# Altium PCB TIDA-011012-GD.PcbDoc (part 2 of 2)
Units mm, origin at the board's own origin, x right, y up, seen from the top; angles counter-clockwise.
Board outline 56 x 53 mm, 4 copper layers (Top Layer, Layer 1, Layer 2, Bottom Layer), stack 1.787 mm thick; 152 components, 63 nets, 416 pads, 728 vias.
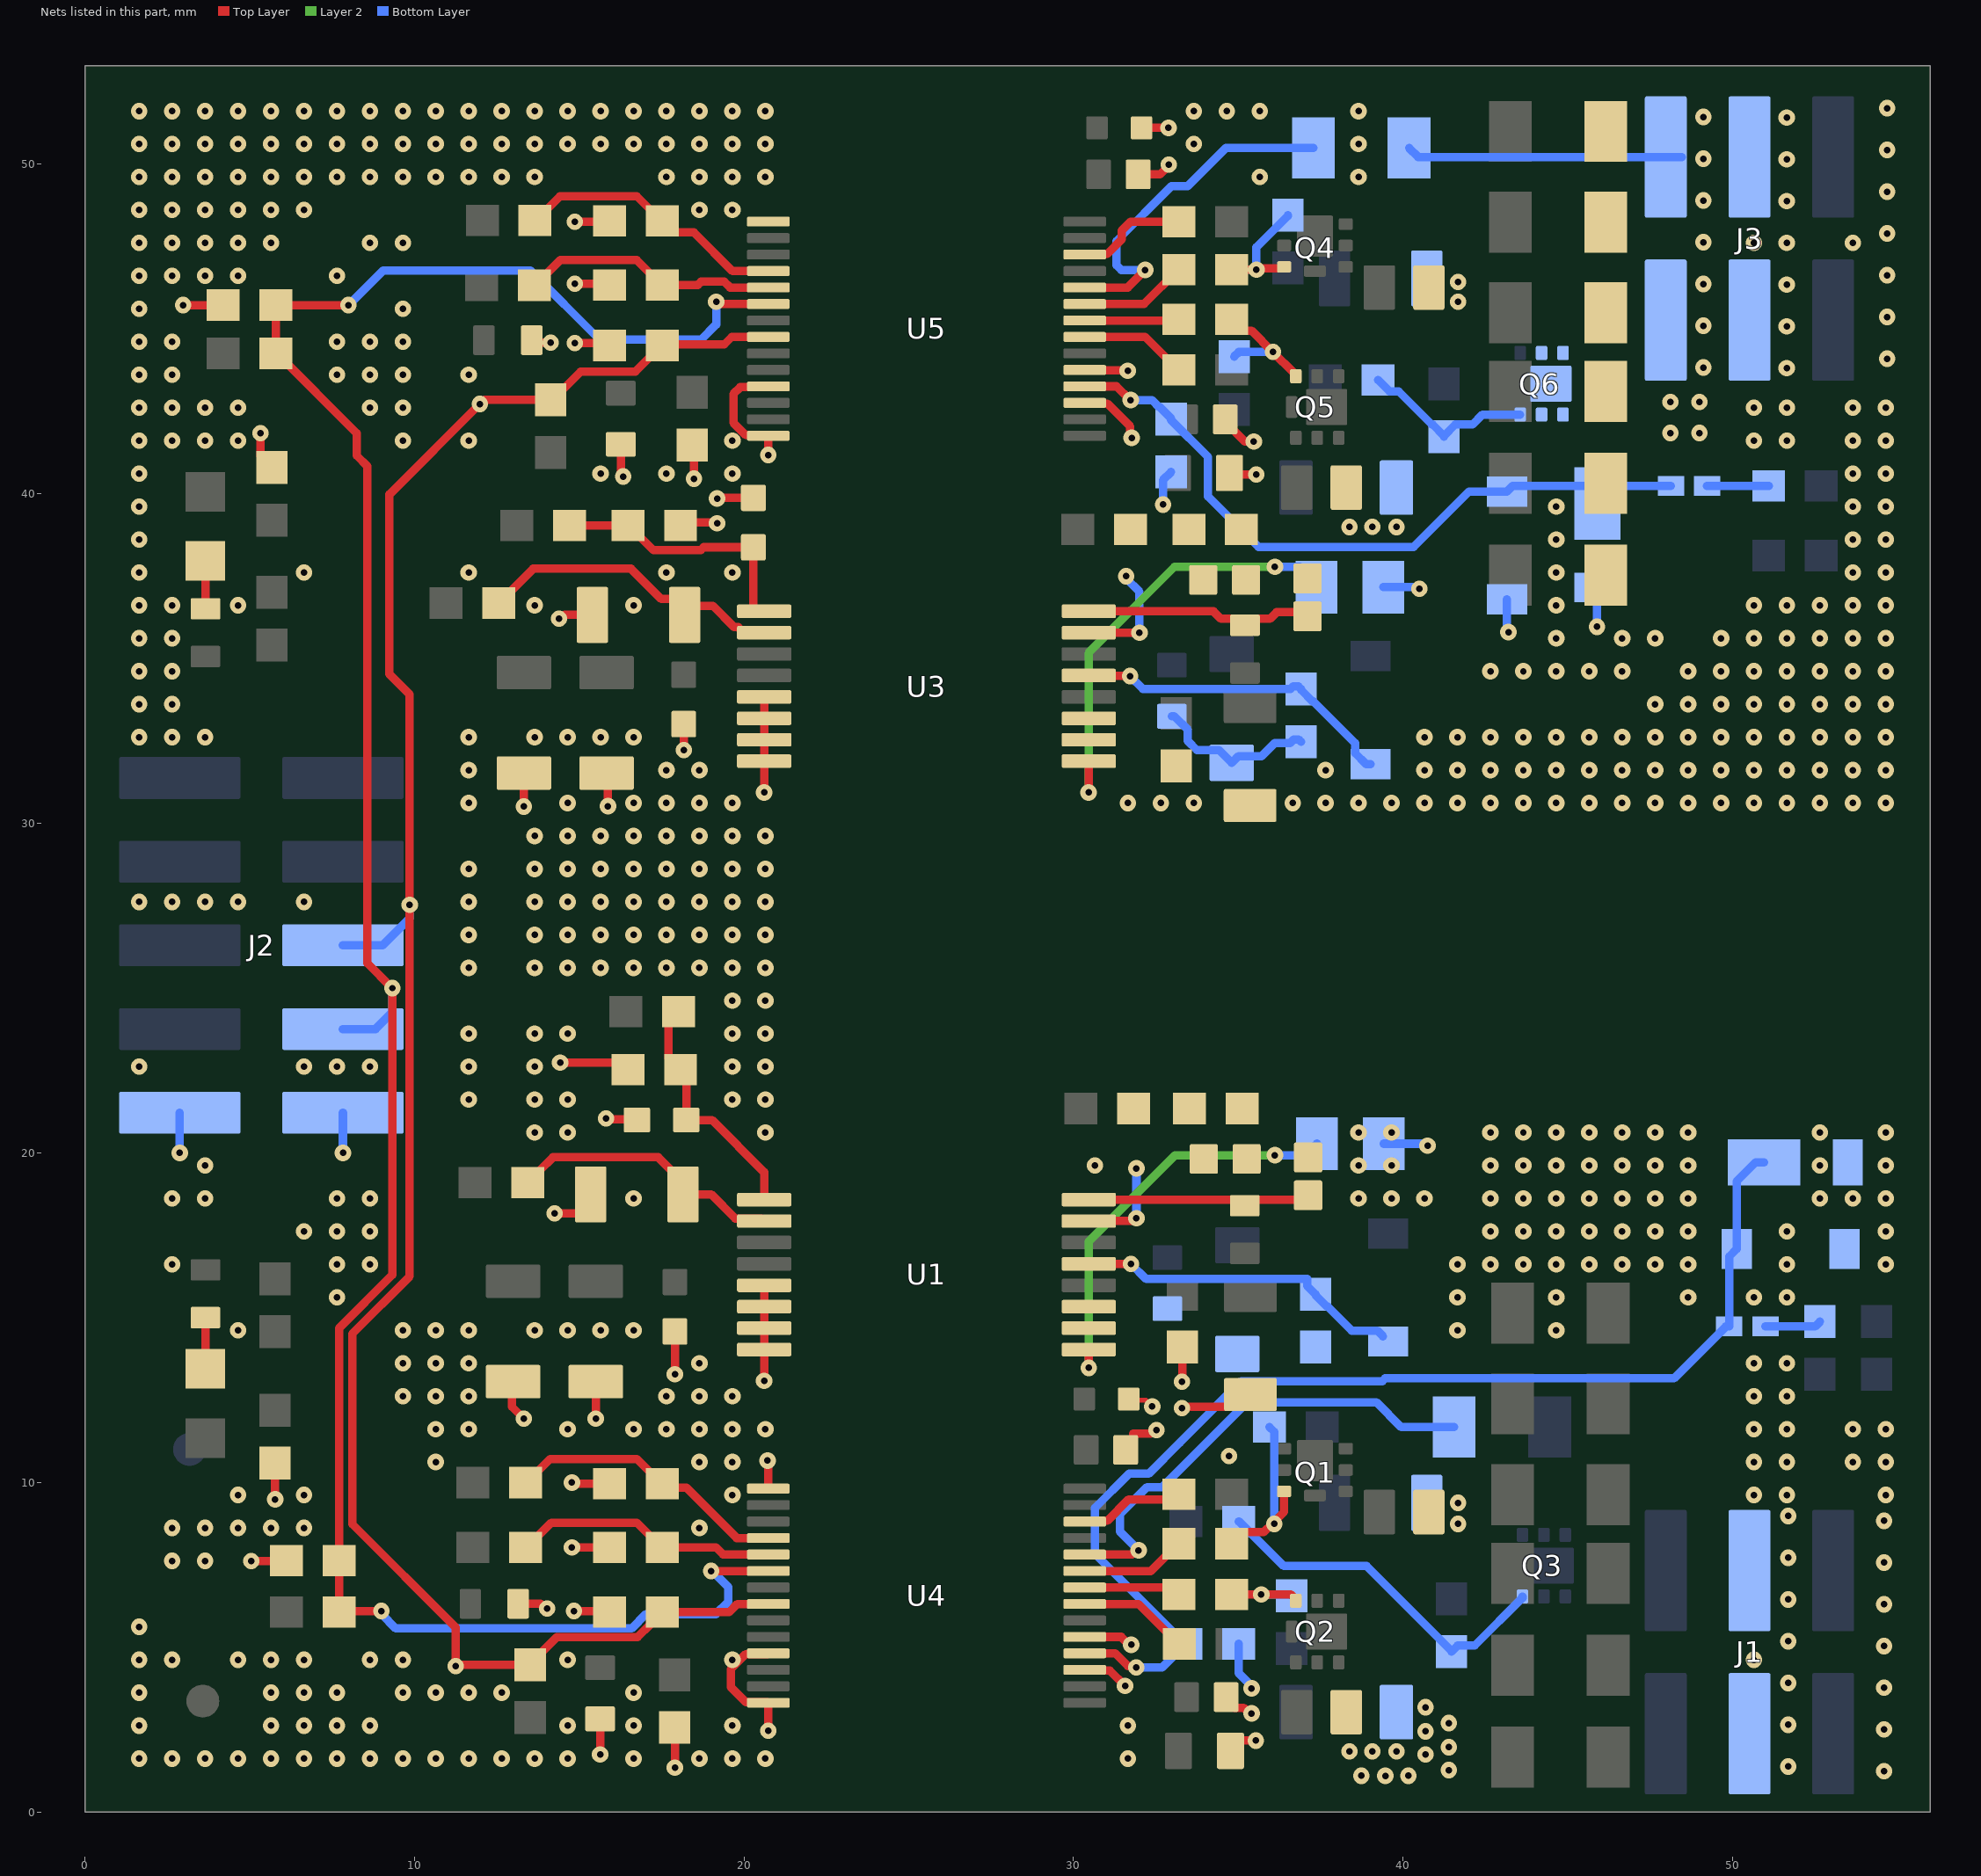
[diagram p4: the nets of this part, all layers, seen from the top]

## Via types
v1: diameter 0.5, hole 0.2, Top Layer to Bottom Layer, tented both sides, 728 vias

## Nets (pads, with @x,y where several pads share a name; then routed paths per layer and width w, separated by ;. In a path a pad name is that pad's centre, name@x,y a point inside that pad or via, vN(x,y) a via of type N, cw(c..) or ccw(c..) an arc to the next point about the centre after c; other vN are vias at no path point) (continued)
G2: J3.5 J3.6 Q6.1 Q6.2 Q6.5 Q6.6 Q6.7 R21.2 R25.2 R33.2 R43.2 R45.2 R46.2 R49.2 | length 8.4
  Bottom Layer w0.254: R43.2@40.181,50.497 40.457,50.222 J3.6@48.46,50.222
  other v1: 48.107,41.846 48.988,41.846 48.107,42.788 48.988,42.788 49.111,43.834 49.111,45.101 49.111,46.368 49.111,47.635 49.111,48.903 49.111,50.17 49.111,51.437
GD_RDY: C33.1 C99.1 J2.7 R15.1 R16.1 U4.6 U5.6 | length 76.8
  Top Layer w0.254: v1(8,45.729) C99.1@5.8,45.729 R16.1@5.8,44.262 5.825,44.262 8.249,41.839 8.249,41.162 8.575,40.836 8.575,25.754 v1(9.328,25) 9.328,16.295 7.712,14.679 C33.1@7.712,7.626 R15.1@7.712,6.06 7.748,6.095 v1(9,6.095) ; v1(19,7.31) U4.6@20.738,7.31 ; v1(19.158,45.833) 19.229,45.762 U5.6@20.738,45.762
  Bottom Layer w0.254: J2.7@7.83,23.757 8.82,23.757 9.328,24.265 v1(9.328,25) ; v1(8,45.729) 9.052,46.781 13.516,46.781 15.614,44.683 18.7,44.683 19.158,45.142 v1(19.158,45.833) ; v1(9,6.095) 9,6 9.432,5.568 16.594,5.568 17.026,6 19.146,6 19.527,6.381 19.527,6.817 19.034,7.31 v1(19,7.31)
GD_RST/EN: C12.1 C98.1 J2.5 R52.1 R59.1 U4.8 U5.8 | length 64
  Top Layer w0.254: C12.1@17.525,44.503 17.5,44.503 16.704,43.708 15.044,43.708 14.187,42.851 14.146,42.851 R59.1@14.136,42.86 12.118,42.86 v1(11.984,42.727) 9.243,39.986 9.243,34.527 9.855,33.915 v1(9.855,27.528) 9.855,16.251 8.116,14.511 8.116,8.733 11.255,5.595 v1(11.255,4.426) 11.297,4.468 R52.1@13.512,4.468 13.512,4.493 14.326,5.308 16.773,5.308 17.152,5.687 17.152,5.712 17.5,6.06 19.55,6.06 19.801,6.31 U4.8@20.738,6.31 ; C12.1@17.865,44.503 17.898,44.536 19.402,44.536 19.628,44.762 U5.8@20.738,44.762
  Bottom Layer w0.254: J2.5@7.83,26.297 9.035,26.297 9.855,27.118 v1(9.855,27.528)
GND: C3.1 C4.1 C5.1 C8.1 C9.1 C12.2 C16.1 C17.1 C18.1 C21.1 C22.1 C27.2 C28.2 C29.1 C30.1 C31.2 C32.2 C33.2 C42.1 C43.1 C46.2 C47.2 C98.2 C99.2 J2.9 J2.10 R5.1 R13.1 R28.2 R47.2 U1.5 U1.6 U1.7 U1.8 U3.5 U3.6 U3.7 U3.8 U4.1 U4.11 U4.14 U5.1 U5.11 U5.14 | length 48.5
  Top Layer w0.254: v1(2.984,45.729) C99.2@4.2,45.729 ; v1(5.048,7.612) 6.099,7.612 C33.2@6.112,7.626 ; v1(5.327,41.839) 5.327,41.152 C32.2@5.675,40.805 ; v1(5.773,9.484) C31.2@5.773,10.582 ; C4.1@12.995,13.056 12.959,13.02 12.959,12.295 v1(13.322,11.932) ; R28.2@13.147,6.314 13.82,6.314 13.962,6.172 v1(14.029,6.172) ; v1(13.322,30.51) C17.1@13.322,31.526 ; R47.2@13.559,44.663 13.63,44.592 v1(14.136,44.592) ; v1(14.254,18.161) 15,18.161 15.348,18.509 C5.1@15.348,18.74 ; v1(14.386,36.212) 14.453,36.212 14.567,36.326 C18.1@15.4,36.326 ; v1(14.421,22.739) 16.262,22.739 R5.1@16.475,22.526 ; v1(14.778,8.023) C27.2@15.925,8.023 ; v1(14.778,9.993) 14.804,9.993 14.838,9.959 C28.2@15.925,9.959 ; v1(14.838,6.095) 15.889,6.095 C98.2@15.925,6.06 ; v1(14.869,44.577) 15.851,44.577 C12.2@15.925,44.503 ; v1(14.869,46.375) 15.89,46.375 C46.2@15.925,46.34 ; v1(14.869,48.258) 15.901,48.258 C47.2@15.925,48.281 ; v1(15.503,11.932) C3.1@15.503,13.056 ; v1(15.635,1.745) C29.1@15.635,2.822 ; v1(15.812,21.047) 15.837,21.022 16.725,21.022 C8.1@16.75,20.997 ; C16.1@15.83,31.526 15.873,31.483 v1(15.873,30.521) ; C42.1@16.262,41.506 16.262,40.6 v1(16.335,40.527) ; C30.1@17.9,2.562 17.904,2.557 v1(17.904,1.345) ; v1(17.904,13.278) 17.904,13.353 C9.1@17.904,14.58 ; R13.1@18.075,39.046 18.159,39.13 19.158,39.13 v1(19.184,39.104) ; C22.1@18.171,33.012 18.171,32.231 v1(18.178,32.223) ; C43.1@18.428,41.481 18.481,41.427 v1(18.481,40.46) ; v1(19.184,39.858) 19.245,39.858 19.267,39.88 C21.1@20.284,39.88 ; v1(20.613,13.08) U1.8@20.613,14.03 U1.7@20.613,14.68 U1.6@20.613,15.33 U1.5@20.613,15.98 ; v1(20.613,30.937) U3.8@20.613,31.887 U3.7@20.613,32.537 U3.6@20.613,33.187 U3.5@20.613,33.837 ; v1(20.715,10.66) 20.738,10.637 U4.1@20.738,9.81 ; v1(20.738,2.46) U4.14@20.738,3.31 20.715,3.333 20.052,3.333 19.597,3.788 19.597,4.332 20.052,4.787 20.715,4.787 U4.11@20.738,4.81 ; v1(20.738,41.178) U5.14@20.738,41.762 20.715,41.785 20.052,41.785 19.679,42.159 19.679,43.032 19.886,43.239 20.715,43.239 U5.11@20.738,43.262
  Bottom Layer w0.254: v1(2.88,20) J2.10@2.88,21.217 ; v1(7.83,20) J2.9@7.83,21.217
  other v1: 1.648,1.616 2.648,1.616 3.648,1.616 4.648,1.616 5.648,1.616 6.648,1.616 7.648,1.616 8.648,1.616 9.648,1.616 10.648,1.616 11.648,1.616 12.648,1.616 13.648,1.616 14.648,1.616 16.648,1.616 18.648,1.616 19.648,1.616 20.648,1.616 1.648,2.616 5.648,2.616 6.648,2.616 7.648,2.616 8.648,2.616 14.648,2.616 16.648,2.616 19.648,2.616 1.648,3.616 5.648,3.616 6.648,3.616 7.648,3.616 9.648,3.616 10.648,3.616 11.648,3.616 12.648,3.616 16.648,3.616 1.648,4.616 2.648,4.616 4.648,4.616 5.648,4.616 6.648,4.616 8.648,4.616 9.648,4.616 14.648,4.616 19.648,4.616 1.648,5.616 2.648,7.616 3.648,7.616 2.648,8.616 3.648,8.616 4.648,8.616 5.648,8.616 6.648,8.616 18.648,8.616 4.648,9.616 6.648,9.616 19.648,9.616 10.648,10.616 18.648,10.616 19.648,10.616 10.648,11.616 11.648,11.616 14.648,11.616 16.648,11.616 17.648,11.616 18.648,11.616 19.648,11.616 20.648,11.616 9.648,12.616 10.648,12.616 11.648,12.616 17.648,12.616 18.648,12.616 19.648,12.616 9.648,13.616 10.648,13.616 11.648,13.616 18.648,13.616 4.648,14.616 9.648,14.616 10.648,14.616 11.648,14.616 13.648,14.616 14.648,14.616 15.648,14.616 16.648,14.616 7.648,15.616 2.648,16.616 7.648,16.616 8.648,16.616 6.648,17.616 7.648,17.616 8.648,17.616 2.648,18.616 3.648,18.616 7.648,18.616 8.648,18.616 16.648,18.616 3.648,19.616 13.648,20.616 14.648,20.616 20.648,20.616 11.648,21.616 13.648,21.616 14.648,21.616 19.648,21.616 20.648,21.616 1.648,22.616 6.648,22.616 7.648,22.616 8.648,22.616 11.648,22.616 13.648,22.616 19.648,22.616 20.648,22.616 11.648,23.616 13.648,23.616 14.648,23.616 19.648,23.616 20.648,23.616 19.648,24.616 20.648,24.616 11.648,25.616 13.648,25.616 14.648,25.616 15.648,25.616 16.648,25.616 17.648,25.616 18.648,25.616 19.648,25.616 20.648,25.616 11.648,26.616 13.648,26.616 14.648,26.616 15.648,26.616 16.648,26.616 17.648,26.616 18.648,26.616 19.648,26.616 20.648,26.616 1.648,27.616 2.648,27.616 3.648,27.616 4.648,27.616 6.648,27.616 11.648,27.616 13.648,27.616 14.648,27.616 15.648,27.616 16.648,27.616 17.648,27.616 18.648,27.616 19.648,27.616 20.648,27.616 11.648,28.616 13.648,28.616 14.648,28.616 15.648,28.616 16.648,28.616 17.648,28.616 18.648,28.616 19.648,28.616 20.648,28.616 13.648,29.616 14.648,29.616 15.648,29.616 16.648,29.616 17.648,29.616 18.648,29.616 19.648,29.616 20.648,29.616 11.648,30.616 14.648,30.616 16.648,30.616 17.648,30.616 18.648,30.616 19.648,30.616 11.648,31.616 17.648,31.616 18.648,31.616 1.648,32.616 2.648,32.616 3.648,32.616 11.648,32.616 13.648,32.616 14.648,32.616 15.648,32.616 16.648,32.616 1.648,33.616 2.648,33.616 1.648,34.616 2.648,34.616 1.648,35.616 2.648,35.616 1.648,36.616 2.648,36.616 4.648,36.616 13.648,36.616 16.648,36.616 1.648,37.616 6.648,37.616 11.648,37.616 17.648,37.616 19.648,37.616 1.648,38.616 1.648,39.616 1.648,40.616 15.648,40.616 17.648,40.616 19.648,40.616 1.648,41.616 2.648,41.616 3.648,41.616 4.648,41.616 9.648,41.616 11.648,41.616 19.648,41.616 1.648,42.616 2.648,42.616 3.648,42.616 4.648,42.616 8.648,42.616 9.648,42.616 1.648,43.616 2.648,43.616 7.648,43.616 8.648,43.616 9.648,43.616 11.648,43.616 1.648,44.616 2.648,44.616 7.648,44.616 8.648,44.616 9.648,44.616 1.648,45.616 9.648,45.616 1.648,46.616 2.648,46.616 3.648,46.616 4.648,46.616 7.648,46.616 1.648,47.616 2.648,47.616 3.648,47.616 4.648,47.616 5.648,47.616 8.648,47.616 9.648,47.616 1.648,48.616 2.648,48.616 3.648,48.616 4.648,48.616 5.648,48.616 6.648,48.616 18.648,48.616 19.648,48.616 1.648,49.616 2.648,49.616 3.648,49.616 4.648,49.616 5.648,49.616 6.648,49.616 7.648,49.616 8.648,49.616 9.648,49.616 10.648,49.616 11.648,49.616 12.648,49.616 13.648,49.616 17.648,49.616 18.648,49.616 19.648,49.616 20.648,49.616 1.648,50.616 2.648,50.616 3.648,50.616 4.648,50.616 5.648,50.616 6.648,50.616 7.648,50.616 8.648,50.616 9.648,50.616 10.648,50.616 11.648,50.616 12.648,50.616 13.648,50.616 14.648,50.616 15.648,50.616 16.648,50.616 17.648,50.616 18.648,50.616 19.648,50.616 20.648,50.616 1.648,51.616 2.648,51.616 3.648,51.616 4.648,51.616 5.648,51.616 6.648,51.616 7.648,51.616 8.648,51.616 9.648,51.616 10.648,51.616 11.648,51.616 12.648,51.616 13.648,51.616 14.648,51.616 15.648,51.616 16.648,51.616 17.648,51.616 18.648,51.616 19.648,51.616 20.648,51.616
KS1: C1.2 C2.1 C10.2 C11.2 C35.1 C36.1 C37.1 C38.2 C39.2 C40.2 C41.2 C55.1 C56.2 D11.2 D12.2 J1.3 J1.4 L1.1 NT1.2 U1.10 U1.11 U4.17 U4.19 | length 13.4
  Top Layer w0.152: C40.2@31.673,12.528 31.71,12.491 32.196,12.491 v1(32.386,12.301)
  Top Layer w0.254: U4.17@30.338,4.31 30.361,4.287 31.101,4.287 v1(31.562,3.826) ; U4.19@30.338,5.31 31.444,5.31 31.682,5.073 v1(31.749,5.073) ; C56.2@31.598,10.964 31.807,11.174 31.807,11.476 32.341,11.476 32.449,11.584 v1(32.516,11.584) ; v1(33.286,12.256) 33.329,12.299 35.002,12.299 C2.1@35.534,12.83 ; v1(33.286,13.055) 33.286,13.061 33.305,13.079 C1.2@33.305,14.103 ; C55.1@34.63,3.483 34.63,3.408 34.878,3.16 35.163,3.16 35.336,2.986 v1(35.403,2.986) ; C37.1@34.762,1.851 34.762,1.882 35.045,2.165 v1(35.534,2.165)
  Bottom Layer w0.254: C41.2@35.004,5.097 35.004,4.213 35.403,3.815 v1(35.403,3.748) ; NT1.2@39.417,20.278 40.655,20.278 40.718,20.214 v1(40.741,20.214)
  other v1: 38.731,1.096 39.462,1.093 40.159,1.096 54.596,1.232 41.387,1.265 51.686,1.376 31.648,1.616 40.68,1.745 38.369,1.834 39.066,1.837 39.797,1.834 41.384,1.962 40.676,2.442 54.596,2.499 31.648,2.616 51.686,2.643 41.387,2.693 40.68,3.173 54.596,3.766 51.686,3.91 50.648,4.616 54.596,5.033 51.686,5.178 54.596,6.3 51.686,6.445 54.596,7.567 51.686,7.712 41.664,8.741 54.596,8.835 51.686,8.979 41.664,9.377 50.648,9.616 51.648,9.616 54.648,9.616 50.648,10.616 51.648,10.616 53.648,10.616 54.648,10.616 34.716,10.8 50.648,11.616 51.648,11.616 53.648,11.616 54.648,11.616 50.648,12.616 51.648,12.616 50.648,13.616 51.648,13.616 41.648,14.616 44.648,14.616 41.648,15.616 44.648,15.616 48.648,15.616 50.648,15.616 51.648,15.616 41.648,16.616 42.648,16.616 43.648,16.616 44.648,16.616 45.648,16.616 46.648,16.616 47.648,16.616 48.648,16.616 51.648,16.616 54.648,16.616 42.648,17.616 43.648,17.616 44.648,17.616 45.648,17.616 46.648,17.616 47.648,17.616 48.648,17.616 51.648,17.616 54.648,17.616 38.648,18.616 39.648,18.616 40.648,18.616 42.648,18.616 43.648,18.616 44.648,18.616 45.648,18.616 46.648,18.616 47.648,18.616 48.648,18.616 52.648,18.616 53.648,18.616 54.648,18.616 30.648,19.616 38.648,19.616 39.648,19.616 42.648,19.616 43.648,19.616 44.648,19.616 45.648,19.616 46.648,19.616 47.648,19.616 48.648,19.616 52.648,19.616 54.648,19.616 38.648,20.616 39.648,20.616 42.648,20.616 43.648,20.616 44.648,20.616 45.648,20.616 46.648,20.616 47.648,20.616 48.648,20.616 52.648,20.616 54.648,20.616
KS2: C14.2 C15.1 C23.2 C24.2 C48.1 C49.1 C50.1 C51.2 C52.2 C53.2 C54.2 C57.1 C58.2 D16.2 D17.2 J3.3 J3.4 L2.1 NT2.2 U3.10 U3.11 U5.17 U5.19 | length 16.7
  Top Layer w0.254: U5.17@30.338,42.762 30.361,42.739 31.023,42.739 31.718,42.045 31.718,41.748 v1(31.765,41.701) ; U5.19@30.338,43.762 30.351,43.749 31.629,43.749 v1(31.643,43.735) ; C58.2@31.96,49.699 32.627,49.699 32.889,49.961 v1(32.889,49.993) ; C53.2@32.063,51.109 v1(32.881,51.109) ; C57.1@34.6,42.262 34.6,42.187 35.202,41.586 v1(35.469,41.586) ; C50.1@34.732,40.631 34.773,40.59 v1(35.544,40.59)
  Bottom Layer w0.254: v1(32.714,39.675) 32.714,40.417 C54.2@32.962,40.665 ; C23.2@32.98,33.25 33.055,33.25 33.466,32.839 33.466,32.501 33.744,32.223 34.414,32.223 C24.2@34.8,31.837 35.005,32.043 35.707,32.043 36.108,32.443 36.575,32.443 36.681,32.549 36.829,32.549 L2.1@36.904,32.475 ; NT2.2@39.399,37.168 40.44,37.168 v1(40.49,37.118) ; D16.2@43.151,36.796 43.151,35.846 v1(43.194,35.803) ; v1(45.883,35.967) 45.883,37.14 D17.2@45.901,37.159
  other v1: 31.648,30.616 32.648,30.616 33.648,30.616 36.648,30.616 37.648,30.616 38.648,30.616 39.648,30.616 40.648,30.616 41.648,30.616 42.648,30.616 43.648,30.616 44.648,30.616 45.648,30.616 46.648,30.616 47.648,30.616 48.648,30.616 49.648,30.616 50.648,30.616 51.648,30.616 52.648,30.616 53.648,30.616 54.648,30.616 37.648,31.616 40.648,31.616 41.648,31.616 42.648,31.616 43.648,31.616 44.648,31.616 45.648,31.616 46.648,31.616 47.648,31.616 48.648,31.616 49.648,31.616 50.648,31.616 51.648,31.616 52.648,31.616 53.648,31.616 54.648,31.616 40.648,32.616 41.648,32.616 42.648,32.616 43.648,32.616 44.648,32.616 45.648,32.616 46.648,32.616 47.648,32.616 48.648,32.616 49.648,32.616 50.648,32.616 51.648,32.616 52.648,32.616 53.648,32.616 54.648,32.616 47.648,33.616 48.648,33.616 49.648,33.616 50.648,33.616 51.648,33.616 52.648,33.616 53.648,33.616 54.648,33.616 42.648,34.616 43.648,34.616 44.648,34.616 45.648,34.616 46.648,34.616 48.648,34.616 49.648,34.616 50.648,34.616 51.648,34.616 52.648,34.616 53.648,34.616 54.648,34.616 44.648,35.616 46.648,35.616 47.648,35.616 49.648,35.616 50.648,35.616 51.648,35.616 52.648,35.616 53.648,35.616 54.648,35.616 44.648,36.616 50.648,36.616 51.648,36.616 52.648,36.616 53.648,36.616 54.648,36.616 44.648,37.616 53.648,37.616 54.648,37.616 44.648,38.616 53.648,38.616 54.648,38.616 38.369,38.997 39.066,39 39.797,38.997 44.648,39.616 53.648,39.616 54.648,39.616 53.648,40.616 54.648,40.616 50.648,41.616 51.648,41.616 53.648,41.616 54.648,41.616 50.648,42.616 51.648,42.616 53.648,42.616 54.648,42.616 51.641,43.816 54.686,44.101 51.641,45.083 54.686,45.368 41.664,45.833 51.641,46.351 41.664,46.43 54.686,46.636 50.648,47.616 51.641,47.618 53.648,47.616 54.686,47.903 51.641,48.885 54.686,49.17 35.648,49.616 38.648,49.616 51.641,50.152 54.686,50.437 33.648,50.616 38.648,50.616 51.641,51.419 33.648,51.616 34.648,51.616 35.648,51.616 38.648,51.616 54.686,51.704
NetC5_2: C5.2 R1.1 U1.2 | length 8.5
  Top Layer w0.254: R1.1@13.437,19.099 13.462,19.099 13.81,19.447 13.81,19.472 14.205,19.867 17.396,19.867 18.148,19.115 C5.2@18.148,18.74 19.004,18.74 19.735,18.008 20.535,18.008 U1.2@20.613,17.93
NetC6_1: C6.1 C7.1 NT1.1 R6.1 U1.9 | length 12.5
  Top Layer w0.254: v1(30.458,13.476) 30.458,14.026 U1.9@30.463,14.03
  Layer 2 w0.254: v1(30.458,13.476) 30.455,13.478 30.455,17.307 33.078,19.929 v1(36.108,19.929)
  Bottom Layer w0.254: v1(36.108,19.929) 37.037,19.929 NT1.1@37.385,20.278
NetC6_2: C6.2 R6.2 R58.1 U1.15 | length 3
  Top Layer w0.254: U1.15@30.463,17.93 31.824,17.93 v1(31.908,18.015)
  Bottom Layer w0.254: v1(31.906,19.53) 31.908,19.527 v1(31.908,18.015)
NetC7_2: C7.2 R4.2 U1.16 | length 7
  Top Layer w0.254: U1.16@30.463,18.58 35.011,18.58 R4.2@35.194,18.398 35.376,18.58 C7.2@36.986,18.58 ; C7.2@36.986,18.58 C7.2@37.117,18.711 C7.2@36.986,18.58
NetC8_2: C8.2 R3.1 R5.2 U1.1 | length 7.5
  Top Layer w0.254: R3.1@18.01,24.283 17.702,23.975 17.702,22.874 18.05,22.526 R5.2@18.075,22.526 18.25,22.351 C8.2@18.25,20.997 ; C8.2@18.225,20.997 19.031,20.997 20.613,19.415 U1.1@20.613,18.58
NetC18_2: C18.2 R8.1 U3.2 | length 9.5
  Top Layer w0.254: R8.1@12.562,36.685 12.587,36.685 12.935,37.033 12.935,37.058 13.605,37.728 16.571,37.728 17.491,36.808 17.852,36.808 18.2,36.46 C18.2@18.2,36.326 ; C18.2@18.2,36.601 19.056,36.601 19.702,35.955 19.825,35.955 19.993,35.787 U3.2@20.613,35.787
NetC19_1: C19.1 C20.1 NT2.1 R14.1 U3.9 | length 13.5
  Top Layer w0.254: v1(30.455,30.937) 30.455,31.88 U3.9@30.463,31.887
  Layer 2 w0.254: v1(30.455,30.937) 30.455,35.178 33.064,37.786 v1(36.108,37.786)
  Bottom Layer w0.254: v1(36.108,37.786) 36.859,37.786 37.367,37.278 NT2.1@37.367,37.168
NetC19_2: C19.2 R10.1 R14.2 U3.15 | length 3.4
  Top Layer w0.254: U3.15@30.463,35.787 v1(32,35.787)
  Bottom Layer w0.254: v1(31.597,37.502) 31.597,37.436 32,37.032 v1(32,35.787)
NetC20_2: C20.2 R12.2 U3.16 | length 7
  Top Layer w0.254: U3.16@30.463,36.437 34.244,36.437 34.471,36.21 35.004,36.21 R12.2@35.202,36.012 35.4,36.21 35.964,36.21 36.16,36.406 36.975,36.406 C20.2@37.098,36.283
NetC21_2: C21.2 R11.1 R13.2 U3.1 | length 8.1
  Top Layer w0.254: R11.1@14.712,39.046 R13.2@16.475,39.046 16.5,39.046 17.252,38.294 18.69,38.294 18.776,38.38 C21.2@20.284,38.38 20.284,36.515 20.362,36.437 U3.1@20.613,36.437
NetC25_2: C25.2 U4.26 | length 3.2
  Top Layer w0.254: U4.26@30.338,8.81 30.361,8.833 31.023,8.833 31.672,9.482 33.043,9.482 C25.2@33.2,9.639
NetC26_2: C26.2 U4.21 | length 3.4
  Top Layer w0.254: U4.21@30.338,6.31 31.968,6.31 33.181,5.097 C26.2@33.206,5.097
NetC27_1: C27.1 R23.2 U4.5 | length 8.1
  Top Layer w0.254: R23.2@13.377,8.023 13.402,8.023 14.154,8.775 16.748,8.775 17.5,8.023 C27.1@17.525,8.023 19.155,8.023 19.368,7.81 U4.5@20.738,7.81
NetC28_1: C28.1 R22.2 U4.4 | length 8.7
  Top Layer w0.254: R22.2@13.377,9.993 13.402,9.993 14.12,10.711 16.748,10.711 17.5,9.959 C28.1@17.525,9.959 17.649,9.836 18.257,9.836 19.782,8.31 U4.4@20.738,8.31
NetC44_2: C44.2 U5.26 | length 3.4
  Top Layer w0.254: U5.26@30.338,47.262 30.361,47.285 31.023,47.285 31.465,47.727 31.465,47.995 31.733,48.262 C44.2@33.2,48.262
NetC45_2: C45.2 U5.21 | length 3.3
  Top Layer w0.254: U5.21@30.338,44.762 32.175,44.762 33.175,43.762 C45.2@33.2,43.762
NetC46_1: C46.1 R42.2 U5.5 | length 7.8
  Top Layer w0.254: R42.2@13.634,46.329 13.659,46.329 14.422,47.092 16.748,47.092 17.5,46.34 C46.1@17.525,46.34 18.599,46.34 18.701,46.441 19.402,46.441 19.581,46.262 U5.5@20.738,46.262
NetC47_1: C47.1 R41.2 U5.4 | length 8.3
  Top Layer w0.254: R41.2@13.659,48.303 13.684,48.303 14.415,49.033 16.748,49.033 17.5,48.281 C47.1@17.525,48.281 17.873,47.933 18.481,47.933 19.652,46.762 U5.4@20.738,46.762
NetD1_1: D1.1 L1.2 U1.13 | length 10
  Top Layer w0.254: U1.13@30.463,16.63 v1(31.743,16.63)
  Bottom Layer w0.254: v1(31.743,16.63) 32.203,16.17 37.086,16.17 37.086,15.961 L1.2@37.344,15.703 37.344,15.678 37.692,15.33 37.717,15.33 38.44,14.607 39.214,14.607 D1.1@39.388,14.434
NetD2_1: D2.1 L2.2 U3.13 | length 9.9
  Top Layer w0.254: U3.13@30.463,34.487 30.471,34.479 31.704,34.479 v1(31.713,34.47)
  Bottom Layer w0.254: v1(31.713,34.47) 32.105,34.078 36.585,34.078 36.662,34.155 36.823,34.155 L2.2@36.904,34.075 36.904,34.05 37.252,33.702 37.277,33.702 38.544,32.434 38.544,32.13 38.875,31.8 D2.1@39.009,31.8
NetD3_1: D3.1 R18.2 | length 1.6
  Top Layer w0.254: D3.1@3.659,13.445 R18.2@3.659,15
NetD4_1: D4.1 R19.2 | length 1.5
  Top Layer w0.254: D4.1@3.655,37.966 3.659,37.962 R19.2@3.659,36.512
NetD10_2: D10.2 R40.1 | length 1.7
  Bottom Layer w0.254: D10.2@50.996,14.732 52.501,14.732 R40.1@52.648,14.878
NetD15_2: D15.2 R57.1 | length 1.9
  Bottom Layer w0.254: D15.2@49.224,40.246 51.088,40.246 R57.1@51.092,40.242
NetQ1_3: Q1.3 R32.2 R37.2 | length 5.6
  Top Layer w0.254: R32.2@34.8,8.139 35.148,8.487 35.769,8.487 36.023,8.741 v1(36.09,8.741) 36.09,8.808 36.388,9.106 Q1.3@36.388,9.724
  Bottom Layer w0.254: R37.2@35.944,11.678 36.09,11.532 v1(36.09,8.741)
NetQ2_3: Q2.3 R29.2 R125.1 | length 3
  Top Layer w0.254: R29.2@34.8,6.599 v1(35.696,6.599) 36.592,6.599 36.744,6.448 Q2.3@36.744,6.408
  Bottom Layer w0.254: v1(35.696,6.599) 36.572,6.599 R125.1@36.619,6.553
NetQ3_3: Q3.3 R34.2 R38.2 | length 11
  Bottom Layer w0.254: R34.2@35.004,8.81 35.029,8.81 36.381,7.458 38.893,7.458 41.467,4.885 R38.2@41.467,4.86 41.656,5.049 42.174,5.049 43.621,6.497 Q3.3@43.621,6.537
NetQ4_3: Q4.3 R51.2 R54.2 | length 3.7
  Top Layer w0.254: R51.2@34.8,46.802 v1@35.587,46.802 ; v1(35.55,46.802) 35.593,46.845 36.345,46.845 Q4.3@36.388,46.887
  Bottom Layer w0.254: v1(35.55,46.802) 35.55,47.484 36.503,48.437 R54.2@36.503,48.462
NetQ5_3: Q5.3 R44.1 R48.2 | length 3.9
  Top Layer w0.254: R48.2@34.8,45.302 35.148,44.954 35.4,44.954 v1(36.048,44.306) 36.696,43.659 36.744,43.611 Q5.3@36.744,43.571
  Bottom Layer w0.254: R44.1@34.875,44.165 35.017,44.306 v1(36.048,44.306)
NetQ6_3: Q6.3 R53.2 R55.1 | length 5.3
  Bottom Layer w0.254: R53.2@39.244,43.456 39.592,43.108 39.867,43.108 40.867,42.108 40.892,42.108 R55.1@41.24,41.76 ; R55.1@41.24,41.735 R55.1@41.24,41.76 ; Q6.3@43.551,42.406 42.409,42.406 42.111,42.108 41.588,42.108 R55.1@41.24,41.76
NetR24_1: R24.1 U4.24 | length 14.9
  Top Layer w0.254: U4.24@30.338,7.81 31.783,7.81 31.908,7.935 v1(31.975,7.935)
  Bottom Layer w0.254: v1(31.975,7.935) 31.403,8.508 31.403,9.029 32.232,9.858 32.693,9.858 35.265,12.43 39.19,12.43 39.942,11.678 R24.1@41.55,11.678
NetR43_1: R43.1 U5.24 | length 10.9
  Top Layer w0.254: U5.24@30.338,46.262 31.643,46.262 v1(32.175,46.795)
  Bottom Layer w0.254: v1(32.175,46.795) 31.45,46.795 31.301,46.943 31.301,47.671 32.966,49.336 33.459,49.336 34.62,50.497 R43.1@37.281,50.497
OC_BOT: C54.1 D15.1 D16.1 D17.1 U5.18 | length 21.3
  Top Layer w0.254: U5.18@30.338,43.262 31.301,43.262 31.718,42.846 v1(31.733,42.846)
  Bottom Layer w0.254: v1(31.733,42.846) 32.381,42.846 32.589,42.638 32.614,42.638 32.962,42.29 C54.1@32.962,42.265 ; C54.1@32.962,42.24 34.076,41.126 34.076,39.924 35.614,38.386 40.314,38.386 41.999,40.071 D16.1@43.151,40.071 43.326,40.246 D15.1@48.124,40.246
OC_TOP: C41.1 D10.1 D11.1 D12.1 U4.18 | length 37.2
  Top Layer w0.254: U4.18@30.338,4.81 31.266,4.81 31.649,4.427 31.855,4.427 v1(31.902,4.38)
  Bottom Layer w0.254: v1(31.902,4.38) 32.687,4.38 33.031,4.724 33.031,4.749 C41.1@33.379,5.097 ; C41.1@33.404,5.097 C41.1@33.379,5.097 ; D12.1@50.945,19.712 50.694,19.712 50.121,19.139 D11.1@50.121,17.082 ; C41.1@33.379,5.097 30.648,7.828 30.648,9.226 31.684,10.262 32.281,10.262 33.222,11.204 35.088,13.07 39.369,13.07 39.454,13.155 48.219,13.155 49.796,14.732 D10.1@49.896,14.732 D11.1@49.896,16.857 ; D11.1@49.896,16.857 D11.1@50.121,17.082 ; D11.1@49.896,16.857 D11.1@50.121,17.082 ; D11.1@49.896,16.857 D11.1@50.121,17.082 ; D11.1@49.896,16.857 D11.1@50.121,17.082 ; D11.1@49.896,16.857 D11.1@50.121,17.082
OUTN_BOT: R51.1 U5.23 | length 3.3
  Top Layer w0.254: U5.23@30.338,45.762 32.135,45.762 33.175,46.802 R51.1@33.2,46.802
OUTN_TOP: R32.1 U4.23 | length 3.2
  Top Layer w0.254: U4.23@30.338,7.31 32.346,7.31 33.175,8.139 R32.1@33.2,8.139
OUTP_BOT: R48.1 U5.22 | length 2.9
  Top Layer w0.254: U5.22@30.338,45.262 33.16,45.262 R48.1@33.2,45.302
OUTP_TOP: R29.1 U4.22 | length 2.9
  Top Layer w0.254: U4.22@30.338,6.81 32.989,6.81 R29.1@33.2,6.599
pads on no net: FID1.33 FID2.1 U4.2 U4.3 U4.9 U4.12 U4.13 U4.16 U4.27 U5.2 U5.3 U5.9 U5.12 U5.13 U5.16 U5.27

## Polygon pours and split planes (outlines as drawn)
GND on Top Layer "TOP_LAYER_GND_P105" (solid, remove dead copper, pour order 105): 0,0 21.435,0 21.435,53 0,53
12V on Top Layer "TOP_LAYER_12V_P104" (solid, remove dead copper, pour order 104): 21.435,35.328 21.441,35.322 21.441,34.322 19.061,34.322 18.178,33.439 9.879,33.439 9.879,35.353
12V on Top Layer "TOP_LAYER_12V_P102" (solid, remove dead copper, pour order 102): 21.435,17.471 21.441,17.465 21.441,16.465 19.061,16.465 18.178,15.582 9.879,15.582 9.879,17.496
KS1 on Top Layer "TOP_LAYER_KS1_P101" (solid, remove dead copper, pour order 101): 29.656,21.989 29.592,21.925 29.592,0 56,0 55.976,0.024 55.976,21.986
G2 on Top Layer "TOP_LAYER_G2_P003" (solid, pour order 3): 49.586,53 45.425,53 45.425,36.556 48.169,36.556 49.586,37.974
BF_OFF_BOT on Top Layer "TOP_LAYER_BF_OFF_BOT_P051" (solid, remove dead copper, pour order 51): 40.987,48.875 41.811,49.699 41.811,51.422 42.389,52 44,52 44,44.533 42.445,44.533 42.215,44.762 42.215,46.604 41.557,47.262 36.102,47.262 36.102,48.875
-5V_BOT on Top Layer "TOP_LAYER_-5V_BOT_P052" (solid, remove dead copper, pour order 52): 36.979,47.047 36.979,44.762 39.777,44.762 39.777,47.047
BF_ON_BOT on Top Layer "TOP_LAYER_BF_ON_BOT_P053" (solid, remove dead copper, pour order 53): 44,44 41.477,44 37.056,44 37.056,41.556 39.981,41.556 41,40.537 41,37.59 42.153,36.437 44,36.437
KS2 on Top Layer "TOP_LAYER_KS2_P054" (solid, remove dead copper, pour order 54): 40.073,46.937 40.073,45.537 41.886,45.537 41.886,46.54 41.489,46.937
+18V_BOT on Top Layer "TOP_LAYER_+18V_BOT_P055" (solid, remove dead copper, pour order 55): 35.926,41.035 35.854,41.035 35.854,38.74 37.287,38.74 37.287,40.757 36.879,41.165 36.879,42.973 36.873,42.98 35.926,42.96
KS2 on Top Layer "TOP_LAYER_KS2_P056" (solid, remove dead copper, pour order 56): 37.703,41.19 37.703,38.74 40.314,38.74 40.314,40.635 39.759,41.19
NetC19_2 on Top Layer "TOP_LAYER_NETC19_2_P063" (solid, remove dead copper, pour order 63): 31.229,39.393 34,39.393 34,36.946 34.034,36.912 34.006,36.885 31.229,36.885
NetC19_1 on Top Layer "TOP_LAYER_NETC19_1_P064" (solid, remove dead copper, pour order 64): 34.607,39.393 34.607,36.936 34.584,36.912 34.638,36.859 37.555,36.859 37.555,38.001 37.171,38.386 35.847,38.386 35.847,39.104 35.559,39.392
+18V_BOT on Top Layer "TOP_LAYER_+18V_BOT_P065" (solid, remove dead copper, pour order 65): 29.655,34.028 29.645,34.019 29.645,33.654 31.995,33.654 33.112,32.537 39.647,32.537 39.647,34.037
+18V_BOT on Top Layer "TOP_LAYER_+18V_BOT_P066" (solid, remove dead copper, pour order 66): 33.946,39.915 33.946,43.015 32.493,43.015 32.493,41.511 32.121,41.139 31.436,41.139 31.436,39.915
-5V_BOT on Top Layer "TOP_LAYER_-5V_BOT_P069" (solid, remove dead copper, pour order 69): 29.647,35.332 29.639,35.324 29.639,34.938 34.089,34.938 34.773,34.254 35.843,34.254 35.843,35.44 35.8,35.483 34.682,35.483 34.089,36.075 32.822,36.075 32.098,35.351
KS2 on Top Layer "TOP_LAYER_KS2_P076" (solid, remove dead copper, pour order 76): 29.955,30.006 29.955,52.955 29.976,52.976 55.976,52.976 55.976,29.994
+18V_TOP on Top Layer "TOP_LAYER_+18V_TOP_P090" (solid, remove dead copper, pour order 90): 29.658,16.165 29.649,16.155 29.649,15.79 31.999,15.79 33.115,14.674 40.624,14.674 40.625,16.174
NetC6_1 on Top Layer "TOP_LAYER_NETC6_1_P094" (solid, remove dead copper, pour order 94): 34.626,21.82 34.626,19.364 34.602,19.34 34.656,19.287 37.574,19.287 37.574,20.429 37.189,20.814 35.865,20.814 35.865,21.532 35.577,21.82
NetC6_2 on Top Layer "TOP_LAYER_NETC6_2_P092" (solid, remove dead copper, pour order 92): 31.229,21.986 34,21.986 34,19.089 34.034,19.055 34.006,19.028 31.229,19.028
-5V_TOP on Top Layer "TOP_LAYER_-5V_TOP_P091" (solid, remove dead copper, pour order 91): 29.647,17.475 29.639,17.467 29.639,17.081 34.291,17.081 34.71,16.663 35.843,16.663 35.843,17.583 35.753,17.673 34.634,17.673 34.089,18.218 32.822,18.218 32.098,17.494
+18V_TOP on Top Layer "TOP_LAYER_+18V_TOP_P088" (solid, remove dead copper, pour order 88): 33.946,0.274 33.946,5.852 32.493,5.852 32.493,4.348 32.493,0.273
KS1 on Top Layer "TOP_LAYER_KS1_P084" (solid, remove dead copper, pour order 84): 37.703,4.027 37.703,1.577 40.314,1.577 40.314,3.472 39.759,4.027
+18V_TOP on Top Layer "TOP_LAYER_+18V_TOP_P083" (solid, remove dead copper, pour order 83): 35.926,3.872 35.854,3.872 35.854,1.577 37.287,1.577 37.287,3.594 36.879,4.002 36.879,5.81 36.873,5.817 35.926,5.797
-5V_TOP on Top Layer "TOP_LAYER_-5V_TOP_P081" (solid, remove dead copper, pour order 81): 36.979,9.883 36.979,7.599 39.777,7.599 39.777,9.883
G1 on Top Layer "TOP_LAYER_G1_P079" (solid, remove dead copper, pour order 79): 45.527,0.795 45.514,0.808 45.514,16.096 47.465,16.096 49.396,14.164 49.396,0.774
BF_ON_TOP on Top Layer "TOP_LAYER_BF_ON_TOP_P078" (solid, remove dead copper, pour order 78): 42.539,7.532 42.539,8.165 43.977,8.165 44,8.142 44,0.49 42,0.49 42,3.061 40.899,4.162 37.377,4.162 37.117,4.423 37.117,6.748 37.29,6.922 41.929,6.922
BF_OFF_TOP on Top Layer "TOP_LAYER_BF_OFF_TOP_P077" (solid, remove dead copper, pour order 77): 41.918,11.448 42.421,11.951 42.421,16.032 44,16.032 44,8.522 42.421,8.522 42.421,9.453 41.83,10.044 36.278,10.044 36.235,10.001 36.247,11.448
GND on Layer 1 "LAYER_1_GND_P106" (solid, remove dead copper, pour order 106): 0,0 21.435,0 21.435,53 0,53
KS1 on Layer 1 "LAYER_1_KS1_P098" (solid, remove dead copper, pour order 98): 29.656,21.989 29.592,21.925 29.592,0 56,0 55.976,0.024 55.976,21.986
KS2 on Layer 1 "LAYER_1_KS2_P074" (solid, remove dead copper, pour order 74): 29.955,30.006 29.955,52.955 29.976,52.976 55.976,52.976 55.976,29.994
KS1 on Layer 2 "LAYER_2_KS1_P100" (solid, remove dead copper, pour order 100): 29.656,21.989 29.592,21.925 29.592,0 56,0 55.976,0.024 55.976,21.986
+18V_TOP on Layer 2 "LAYER_2_+18V_TOP_P097" (solid, remove dead copper, pour order 97): 38.877,16.096 38.877,5.106 35.333,1.561 32.311,1.561 32.311,0.274 36.221,0.274 40.314,4.366 40.314,16.096
-5V_TOP on Layer 2 "LAYER_2_-5V_TOP_P096" (solid, remove dead copper, pour order 96): 30.284,12.751 32.705,10.33 35.083,10.33 36.619,11.865 36.619,18.039 36.742,18.162 38.526,18.162 38.677,18.011 38.677,7.612 32.468,7.612 31.088,6.232 31.088,0.98 29.708,0.98 29.476,1.212 29.476,12.751
+18V_BOT on Layer 2 "LAYER_2_+18V_BOT_P062" (solid, remove dead copper, pour order 62): 38.002,32.557 37.989,32.569 37.989,37.14 36.96,38.169 31.107,38.169 30.324,37.387 29.72,37.387 29.72,39.303 30.648,40.231 31.301,40.231 31.301,41.004 31.436,41.139 31.44,41.134 32.42,41.134 32.42,39.586 32.668,39.339 37.879,39.339 39.647,37.571 39.647,32.537
-5V_BOT on Layer 2 "LAYER_2_-5V_BOT_P072" (solid, remove dead copper, pour order 72): 40.037,34.212 42.1,34.212 42.191,34.303 42.191,45.103 39.731,45.103 38.93,45.904 38.858,45.833 31.077,45.833 30.648,46.262 30.648,51.559 29.79,51.559 29.639,51.409 29.639,40.527 31.097,40.527 31.194,40.624 31.194,44.262 38.512,44.262 40.037,42.738
KS2 on Layer 2 "LAYER_2_KS2_P073" (solid, remove dead copper, pour order 73): 29.979,30.006 29.979,52.979 30,53 56,53 56,29.994
GND on Layer 2 "LAYER_2_GND_P039" (solid, remove dead copper, pour order 39): 0,0 21.435,0 21.435,53 0,53
G1 on Bottom Layer "BOTTOM_LAYER_G1_P080" (solid, remove dead copper, pour order 80): 49.243,12.665 49.243,0.572 44,0.572 44,12.665
G2 on Bottom Layer "BOTTOM_LAYER_G2_P059" (solid, remove dead copper, pour order 59): 44,52.211 49.621,52.211 49.621,41.421 44,41.421
GND on Bottom Layer "BOTTOM_LAYER_GND_P038" (solid, remove dead copper, pour order 38): 0,0 21.435,0 21.435,53 0,53
KS1 on Bottom Layer "BOTTOM_LAYER_KS1_P099" (solid, remove dead copper, pour order 99): 29.656,21.989 29.592,21.925 29.592,0 56,0 55.976,0.024 55.976,21.986
-5V_TOP on Bottom Layer "BOTTOM_LAYER_-5V_TOP_P095" (solid, remove dead copper, pour order 95): 32.106,16.453 32.197,16.543 32.197,17.527 32.803,18.134 40.624,18.134 40.624,16.453
+18V_BOT on Bottom Layer "BOTTOM_LAYER_+18V_BOT_P058" (solid, remove dead copper, pour order 58): 35.854,41.035 35.854,38.711 37.269,38.711 37.269,41.035
KS2 on Bottom Layer "BOTTOM_LAYER_KS2_P061" (solid, remove dead copper, pour order 61): 39.267,41.19 39.267,40.072 38.991,39.796 38.161,39.796 37.703,39.339 37.703,38.74 40.314,38.74 40.314,41.19
-5V_BOT on Bottom Layer "BOTTOM_LAYER_-5V_BOT_P067" (solid, remove dead copper, pour order 67): 40.714,42.839 43.669,42.839 43.669,45.103 40.714,45.103
-5V_BOT on Bottom Layer "BOTTOM_LAYER_-5V_BOT_P068" (solid, remove dead copper, pour order 68): 37.012,47.45 37.012,44.776 38.877,44.776 38.877,47.45
-5V_BOT on Bottom Layer "BOTTOM_LAYER_-5V_BOT_P070" (solid, remove dead copper, pour order 70): 32.18,34.487 32.189,34.496 32.189,35.48 32.795,36.087 41.791,36.087 41.791,34.487
KS2 on Bottom Layer "BOTTOM_LAYER_KS2_P075" (solid, remove dead copper, pour order 75): 29.955,30.006 29.955,52.955 29.976,52.976 55.976,52.976 55.976,29.994
-5V_TOP on Bottom Layer "BOTTOM_LAYER_-5V_TOP_P089" (solid, remove dead copper, pour order 89): 43.8,8.696 43.771,8.725 43.736,8.69 43.081,8.69 42.346,7.955 40.95,7.955 40.95,5.964 40.992,5.923 41.942,5.939 42.396,6.394 42.784,6.394 43.536,7.145 43.8,7.145
+18V_TOP on Bottom Layer "BOTTOM_LAYER_+18V_TOP_P087" (solid, remove dead copper, pour order 87): 35.878,5.473 35.878,1.548 37.293,1.548 37.293,5.473
-5V_TOP on Bottom Layer "BOTTOM_LAYER_-5V_TOP_P082" (solid, remove dead copper, pour order 82): 37.012,12.153 37.012,7.612 38.877,7.612 38.877,12.153

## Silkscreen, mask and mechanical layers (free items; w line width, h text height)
Top Overlay:
  text "'.PRJ_Number'.PCB_Rev" at 22.448,25.564 h2
  text "Danger High Voltage" at 52.991,24.923 h1.5 r90
M1 Board Outline:
  the board outline again, w0.5
M2 Board Dimensions:
  rectangle: 3.175,-10.16 12.7,-6.985
  rectangle: 0,-6.985 3.175,-3.81
  lines w0.178: 0,-6.985 25.4,-6.985 ; 3.175,-10.16 3.175,-3.81 ; 6.35,-10.16 6.35,-3.81 ; 12.7,-10.16 12.7,-3.81 ; 19.05,-10.16 19.05,-3.81 ; 0,-10.16 0,-3.81 25.4,-3.81 25.4,-10.16 0,-10.16
M5 Assembly Top:
  lines w0.254: -7.417,-23.626 160.223,-23.626 ; -7.417,-18.462 160.274,-18.462 ; -7.417,-13.297 -7.417,-28.791 94.31,-28.791 160.274,-28.791 160.274,-13.297 -7.404,-13.297 -7.404,-28.791 32.614,-28.791 ; 55.194,-28.791 55.194,-13.297 ; 87.376,-18.462 87.376,-13.297 ; 108.712,-18.462 108.712,-13.297 ; 124.511,-28.956 124.511,-23.804
  text "COMPONENTS MARKED 'DNP' SHOULD NOT BE POPULATED." at 29.299,-8.09 h1.52
  text "ASSEMBLY VARIANT:" at 29.286,-11.024 h1.52
  text ".VariantName" at 55.601,-11.024 h1.52
  text "PCB VIEWED FROM TOP SIDE" at -5.804,-16.654 h1.52
  text "BOARD #:" at 57.099,-16.654 h1.52
  text ".PRJ_Number" at 70.955,-16.654 h1.52
  text "REV:" at 92.405,-16.654 h1.52
  text ".PCB_Rev" at 99.809,-16.654 h1.52
  text "SVN REV:" at 113.69,-16.654 h1.52
  text ".VersionControl_RevNumber" at 126.543,-16.654 h1.52
  text "PLOT NAME =" at -5.804,-27.034 h1.52
  text ".plot_File_Name" at 14.656,-27.034 h1.52
  text "GENERATED    :" at 57.15,-27.034 h1.52
  text ".Print_Date" at 79.235,-27.034 h1.52
  text ".Print_Time" at 97.752,-27.034 h1.52
  text "TEXAS INSTRUMENTS" at 129.87,-27.034 h1.52
M6 Assembly Bottom:
  lines w0.254: -7.429,-18.474 160.261,-18.474 ; -7.379,-23.639 160.261,-23.639 ; 28.334,-28.969 28.334,-23.817 ; 44.133,-18.474 44.133,-13.31 ; 65.468,-18.474 65.468,-13.31 ; 97.65,-28.804 97.65,-13.31 ; 120.231,-28.804 160.249,-28.804 160.249,-13.31 -7.429,-13.31 -7.429,-28.804 58.534,-28.804 160.261,-28.804 160.261,-13.31
  text "COMPONENTS MARKED 'DNP' SHOULD NOT BE POPULATED." at 154.991,-8.077 h1.52
  text ".VariantName" at 128.473,-11.024 h1.52
  text "ASSEMBLY VARIANT:" at 154.864,-11.024 h1.52
  text ".VersionControl_RevNumber" at 26.302,-16.667 h1.52
  text "SVN REV:" at 39.154,-16.667 h1.52
  text ".PCB_Rev" at 53.035,-16.667 h1.52
  text "REV:" at 60.439,-16.667 h1.52
  text ".PRJ_Number" at 81.89,-16.667 h1.52
  text "BOARD #:" at 95.745,-16.667 h1.52
  text "PCB VIEWED FROM BOTTOM SIDE" at 158.648,-16.667 h1.52
  text "TEXAS INSTRUMENTS" at 22.974,-27.047 h1.52
  text ".Print_Time" at 55.093,-27.047 h1.52
  text ".Print_Date" at 73.609,-27.047 h1.52
  text "GENERATED    :" at 95.694,-27.047 h1.52
  text ".plot_File_Name" at 138.189,-27.047 h1.52
  text "PLOT NAME =" at 158.648,-27.047 h1.52
M9 Title Sheet:
  drawing of 56 lines, arcs and shapes, not listed
  text "1" at 26.882,339.887 h1.78
  text "2" at 111.354,339.887 h1.78
  text "3" at 195.936,339.887 h1.78
  text "4" at 280.645,339.887 h1.78
  text "5" at 365.1,339.887 h1.78
  text "6" at 449.809,339.887 h1.78
  text "A" at -11.76,294.726 h1.78
  text "A" at 488.62,294.726 h1.78
  text "B" at -11.76,199.476 h1.78
  text "B" at 488.62,199.476 h1.78
  text "C" at -11.76,104.226 h1.78
  text "C" at 488.62,104.226 h1.78
  text "D" at -11.76,8.976 h1.78
  text "D" at 488.62,8.976 h1.78
  text "PROJECT TITLE:" at 410.032,6.817 h1.14
  text ".PRJ_Title" at 411.302,3.431 h1.78
  text "DESIGNED FOR:" at 410.032,-0.828 h1.14
  text ".PRJ_Customer" at 411.302,-4.384 h1.78
  text "FILE NAME:" at 410.032,-8.448 h1.14
  text ".PCB_File_Name_No_Path" at 411.302,-11.496 h1.78
  text "Texas Instruments (TI) and/or its licensors do not warrant the accuracy or completeness of this specification" at 283.807,-15.607 h1.14
  text "ENGINEER:" at 410.032,-15.814 h1.14
  text "LAYOUT BY:" at 448.259,-15.814 h1.14
  text "or any information contained therein. TI and/or its licensors do not warrant that this design will meet" at 282.664,-18.469 h1.14
  text ".PRJ_Engineer" at 411.302,-19.751 h1.78
  text ".PCB_Layout" at 449.542,-19.751 h1.78
  text "the specifications, will be suitable for your application or fit for any particular purpose, or will operate in" at 282.664,-21.33 h1.14
  text ".Layer_Name" at 14.656,-21.806 h1.52
  text "ALTIUM DESIGNER VERSION:" at 448.259,-23.688 h1.14
  text "an implementation. TI and/or its licensors do not warrant that the design is production worthy. You should" at 282.664,-24.192 h1.14
  text "completely validate and test your design implementation to confirm the system functionality for your application." at 283.807,-27.054 h1.14
  text ".print_Scale" at 411.302,-27.075 h1.78
  text ".Application_BuildNumber" at 449.542,-27.075 h1.78
  text "1" at 26.882,-33.493 h1.78
  text "2" at 111.354,-33.493 h1.78
  text "3" at 195.936,-33.493 h1.78
  text "4" at 280.645,-33.493 h1.78
  text "5" at 365.1,-33.493 h1.78
  text "6" at 449.809,-33.493 h1.78
M10 Fab Notes:
  drawing of 189 lines, arcs and shapes, not listed
  text "DESIGN INFORMATION" at 436.322,161.675 h1.52
  text "MIN. TRACK WIDTH:" at 419.95,158.319 h1.52
  text "8" at 447.794,158.32 h1.52
  text "MIL" at 451.725,158.319 h1.52
  text "MIN. CLEARANCE:" at 419.95,155.167 h1.52
  text "MIL" at 451.725,155.167 h1.52
  text "7.874" at 443.475,155.05 h1.52
  text "MIN. VIA PAD SIZE:" at 419.95,152.014 h1.52
  text "24" at 447.033,152.014 h1.52
  text "MIL" at 451.725,152.014 h1.52
  text "0.05mm (2MIL)" at 437.603,148.714 h1.52
  text "MINIMUM ANNULAR RING" at 411.587,148.506 h1.52
  text "EXTERNAL" at 455.586,148.506 h1.52
  text "PER" at 416.667,145.708 h1.52
  text "IPC-D-275 CLASS 2 LEVEL C" at 422.255,145.708 h1.52
  text "MIL, HOLES" at 460.056,143.156 h1.52
  text "+/-" at 450.088,142.938 h1.52
  text "+/-" at 471.78,142.938 h1.52
  text "REGISTRATION TOLERANCES:" at 411.587,142.911 h1.52
  text "METAL" at 442.062,142.911 h1.52
  text "5" at 456.697,142.911 h1.52
  text "3" at 477.855,142.911 h1.52
  text "MIL" at 480.808,142.911 h1.52
  text "HOLE SIZE TOLERANCE (UNLESS OTHERWISE SPECIFIED):" at 411.587,140.414 h1.52
  text "+/-" at 471.78,140.341 h1.52
  text "3" at 477.855,140.314 h1.52
  text "MIL" at 480.808,140.314 h1.52
  text "MATERIAL:" at 409.688,136.818 h1.52
  text "FR-4 High Tg" at 434.744,133.553 h1.52
  text "X" at 431.075,133.35 h1.52
  text "FR-4" at 420.382,133.235 h1.52
  text "OTHER" at 458.177,133.235 h1.52
  text "62 MIL (1.6mm) +/-10%" at 428.512,129.602 h1.52
  text "X" at 425.462,129.54 h1.52
  text "THICKNESS:" at 411.587,129.394 h1.52
  text "OTHER" at 461.149,129.394 h1.52
  text "TOLERANCE:" at 411.587,125.88 h1.52
  text "X" at 433.133,125.88 h1.52
  text "ANSI IPC-6012 TYPE 3 CLASS 2" at 437.654,125.88 h1.52
  text "OTHER +/-" at 437.654,122.218 h1.52
  text "BOW & TWIST:" at 411.587,118.53 h1.52
  text "X" at 433.133,118.53 h1.52
  text "ANSI IPC-6012 TYPE 3 CLASS 2" at 437.654,118.53 h1.52
  text "OTHER +/-" at 437.654,114.804 h1.52
  text "DRILLING:" at 409.688,111.486 h1.52
  text "NC_DRILL FILES" at 454.418,108.815 h1.52
  text "REFERENCE:" at 411.587,108.715 h1.52
  text "X" at 428.281,108.712 h1.52
  text "AS SHOWN" at 432.802,108.715 h1.52
  text "X" at 451.167,108.715 h1.52
  text "OTHER" at 461.987,105.101 h1.52
  text "PTH COPPER THICKNESS:" at 411.579,105.012 h1.52
  text "X" at 440.516,105.012 h1.52
  text "20-30 um" at 443.767,105.012 h1.52
  text "BOARD FINISH:" at 409.688,101.263 h1.52
  text "SILKSCREEN:" at 413.631,98.466 h1.52
  text "X" at 437.959,98.466 h1.52
  text "TOP" at 440.93,98.466 h1.52
  text "X" at 450.913,98.466 h1.52
  text "BOTTOM" at 453.91,98.466 h1.52
  text "SILKSCREEN COLOR:" at 413.631,94.524 h1.52
  text "X" at 437.933,94.524 h1.52
  text "WHITE" at 440.93,94.524 h1.52
  text "OTHER" at 453.91,94.524 h1.52
  text "X" at 441.261,90.88 h1.52
  text "GREEN" at 444.258,90.88 h1.52
  text "OTHER" at 459.955,90.88 h1.52
  text "SOLDER RESIST COLOR:" at 413.631,90.706 h1.52
  text "X" at 441.261,86.962 h1.52
  text "MATTE" at 444.258,86.962 h1.52
  text "SEMI-GLOSS" at 459.943,86.946 h1.52
  text "IMMERSION GOLD (ENIG)" at 436.638,82.574 h1.52
  text "ENEPIG" at 470.611,82.39 h1.52
  text "SURFACE FINISH:" at 409.688,82.365 h1.52
  text "X" at 432.117,82.365 h1.52
  text "IMM. TIN/SILVER OR EQUIV" at 418.059,78.877 h1.52
  text "OTHER" at 454.418,78.777 h1.52
  text "ARRAY/PANEL:" at 409.688,74.831 h1.52
  text "CUT AND TRIM PER M1 BOARD OUTLINE" at 436.638,74.622 h1.52
  text "N.C. ROUTE" at 436.638,71.168 h1.52
  text "X" at 454.113,71.168 h1.52
  text "V. SCORE" at 458.634,71.168 h1.52
  text "CERTIFICATION:" at 409.688,67.888 h1.52
  text "MATERIALS AND WORKMANSHIP FOR ALL PCBS" at 428.103,67.888 h1.52
  text "TO MEET OR EXCEED THE REQUIREMENTS OF:" at 428.103,65.499 h1.52
  text "X" at 418.896,62.232 h1.52
  text "ANSI IPC-A-600F CLASS ->" at 422.147,62.232 h1.52
  text "X" at 464.006,62.232 h1.52
  text "2" at 466.8,62.232 h1.52
  text "1" at 458.799,62.194 h1.52
  text "3" at 475.792,62.194 h1.52
  text "X" at 439.521,58.481 h1.52
  text "RoHS" at 442.772,58.481 h1.52
  text "OTHER" at 459.14,58.481 h1.52
  text "PER ORDER" at 469.225,58.481 h1.52
  text "ALL BOARDS MUST MEET OR EXCEED UL94-V0 REQUIREMENTS." at 410.388,54.574 h1.52
  text "PCB MUST BEAR THE UL94V-0 UL REGISTERED MATERIAL ID NUMBER" at 410.388,51.626 h1.52
  text "ADDITIONAL REQUIREMENTS:" at 409.688,47.322 h1.52
  text "MICROSECTION:" at 411.587,44.601 h1.52
  text "YES" at 434.593,44.601 h1.52
  text "REQUIRED" at 456.475,40.935 h1.52
  text "BARE BOARD ELEC. TEST:" at 411.587,40.863 h1.52
  text "NONE" at 444.753,40.863 h1.52
  text "X" at 453.478,40.863 h1.52
  text "PER ORDER" at 471.512,40.863 h1.52
  text "XX MIL VIAS REQUIRE NON-CONDUCTIVE FILL AND PLANARIZE" at 415.858,35.657 h1.5
  text "XX MIL VIAS REQUIRE CONDUCTIVE FILL AND PLANARIZE" at 416.062,33.016 h1.52
  text "OUTER XX MIL TRACES REQUIRE 50 OHM SINGLE-ENDED IMPEDANCE" at 416.037,28.866 h1.47
  text "LAYER 2 & 3 (INNER LAYERS) XX MIL WIDE, XX MIL SPACE / TRACES REQUIRE 100 OHM DIFFERENTIAL IMPEDANCE" at 415.833,22.879 h1.52
M11 Gerber Information:
  lines w0.254: -7.417,-23.626 160.223,-23.626 ; -7.417,-18.462 160.274,-18.462 ; -7.417,-13.297 -7.417,-28.791 94.31,-28.791 160.274,-28.791 160.274,-13.297 -7.404,-13.297 -7.404,-28.791 32.614,-28.791 ; 55.194,-28.791 55.194,-13.297 ; 87.376,-18.462 87.376,-13.297 ; 108.712,-18.462 108.712,-13.297 ; 124.511,-28.956 124.511,-23.804
  text "ALL ARTWORK VIEWED FROM TOP SIDE" at -5.804,-16.654 h1.52
  text "BOARD #:" at 57.099,-16.654 h1.52
  text ".PRJ_Number" at 70.955,-16.654 h1.52
  text "REV:" at 92.405,-16.654 h1.52
  text ".PCB_Rev" at 99.809,-16.654 h1.52
  text "SVN REV:" at 113.69,-16.654 h1.52
  text ".VersionControl_RevNumber" at 126.543,-16.654 h1.52
  text "LAYER NAME =" at -5.804,-21.806 h1.52
  text "PLOT NAME =" at -5.804,-27.034 h1.52
  text ".plot_File_Name" at 14.656,-27.034 h1.52
  text "GENERATED    :" at 57.15,-27.034 h1.52
  text ".Print_Date" at 79.235,-27.034 h1.52
  text ".Print_Time" at 97.752,-27.034 h1.52
  text "TEXAS INSTRUMENTS" at 129.87,-27.034 h1.52
M12 Stackup:
  drawing of 295 lines, arcs and shapes, not listed
  text "Layer" at 370.969,332.524 h1.52
  text "Name" at 381.38,332.524 h1.52
  text "Material" at 404.996,332.524 h1.52
  text "Thickness" at 426.834,332.524 h1.52
  text "Constant" at 443.34,332.524 h1.52
  text "Board Layer Stack" at 457.814,332.524 h1.52
  text "Top Overlay" at 381.38,329.476 h1.52
  text "Top Solder" at 381.38,326.428 h1.52
  text "Solder Resist" at 404.996,326.428 h1.52
  text "0,40mil" at 426.834,326.428 h1.52
  text "3.5" at 443.34,326.428 h1.52
  text "1" at 370.969,323.38 h1.52
  text "Top Layer" at 381.38,323.38 h1.52
  text "1,40mil" at 426.834,323.38 h1.52
  text "Dielectric 1" at 381.38,320.332 h1.52
  text "PP-006" at 404.996,320.332 h1.52
  text "2,80mil" at 426.834,320.332 h1.52
  text "4.1" at 443.34,320.332 h1.52
  text "2" at 370.969,317.284 h1.52
  text "Layer 1" at 381.38,317.284 h1.52
  text "CF-004" at 404.996,317.284 h1.52
  text "1,38mil" at 426.834,317.284 h1.52
  text "Dielectric1" at 381.38,314.236 h1.52
  text "FR-4 High Tg" at 404.996,314.236 h1.52
  text "59,20mil" at 426.834,314.236 h1.52
  text "4.8" at 443.34,314.236 h1.52
  text "3" at 370.969,311.188 h1.52
  text "Layer 2" at 381.38,311.188 h1.52
  text "CF-004" at 404.996,311.188 h1.52
  text "1,38mil" at 426.834,311.188 h1.52
  text "Dielectric 2" at 381.38,308.14 h1.52
  text "PP-006" at 404.996,308.14 h1.52
  text "2,80mil" at 426.834,308.14 h1.52
  text "4.1" at 443.34,308.14 h1.52
  text "4" at 370.969,305.092 h1.52
  text "Bottom Layer" at 381.38,305.092 h1.52
  text "1,40mil" at 426.834,305.092 h1.52
  text "Bottom Solder" at 381.38,302.044 h1.52
  text "Solder Resist" at 404.996,302.044 h1.52
  text "0,40mil" at 426.834,302.044 h1.52
  text "3.5" at 443.34,302.044 h1.52
  text "Bottom Overlay" at 381.38,298.996 h1.52
Drill Drawing:
  lines w0.254: 844.82,316.071 846.223,316.071 846.223,317.474 844.82,317.474 844.82,316.071
  lines w0.305: 843.547,315.123 925.647,315.123 ; 843.547,318.281 925.647,318.281 ; 852.129,311.966 852.129,321.438 ; 860.565,311.966 860.565,321.438 ; 876.735,311.966 876.735,321.438 ; 883.319,311.966 883.319,321.438 ; 892.85,311.966 892.85,321.438 ; 911.256,311.966 911.256,321.438 ; 843.547,311.966 925.647,311.966 925.647,321.438 843.547,321.438 843.547,311.966
  text "Symbol" at 845.442,319.228 h1.83
  text "Quantity" at 853.076,319.228 h1.83
  text "Finished Hole Size" at 861.512,319.228 h1.83
  text "Plated" at 877.683,319.228 h1.83
  text "Hole Type" at 884.266,319.228 h1.83
  text "Drill Layer Pair" at 893.798,319.228 h1.83
  text "Hole Tolerance" at 912.203,319.228 h1.83
  text "728" at 853.076,316.071 h1.52
  text "7,87mil (0,200mm)" at 861.512,316.071 h1.52
  text "PTH" at 877.683,316.071 h1.52
  text "Round" at 884.266,316.071 h1.52
  text "Top Layer - Bottom Layer" at 893.798,316.071 h1.52
  text "728 Total" at 853.076,312.913 h1.52

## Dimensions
0,-10.16 to 25.4,-10.16 on M2 Board Dimensions
56,0 to 0,53 on M2 Board Dimensions
0,0 to 0,53 on M2 Board Dimensions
